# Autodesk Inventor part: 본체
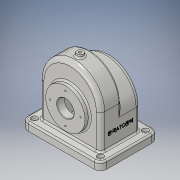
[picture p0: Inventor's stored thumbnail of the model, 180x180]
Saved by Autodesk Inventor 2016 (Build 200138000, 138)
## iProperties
Created: 2017-11
Part Number: 본체
Material: 알루미늄 6061
Document SubType Name: Modeling
Designer: Administrator
Density: 2.7 g/cm^3
Appearance: 알루미늄 - 평지
Mass: 1074.96 g
Surface Area: 1183.3 cm^2
Volume: 398.134 cm^3
Author: Administrator
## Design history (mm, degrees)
sketch "스케치2"
  geometry: L1 (55, 75)-(-55, 75); L2 (-55, 75)-(-55, -75); L3 (-55, -75)-(55, -75); L4 (55, -75)-(55, 75); L5 (55, 75)-(-55, -75); L6 (-55, 75)-(55, -75); 1 further point
  constraints: 12 end point, 2 midpoint, 2 parallel, 1 horizontal, 1 perpendicular
  dimensions: "d1" = 110 distance of L2.end L3.end; "d2" = 150 distance of L3.end L1.start
extrude "돌출1" new body sketch "스케치2" distance "d3" = 15; taper "d4" = 0 deg
fillet "모깎기1" dims "d5" = 12
sketch "스케치3"
  geometry: A1 r 12 centre (-43, -63) between (-55, -63) and (-43, -75) reference; A2 r 12 centre (-43, 63) between (-43, 75) and (-55, 63) reference; A3 r 12 centre (43, -63) between (43, -75) and (55, -63) reference; A4 r 12 centre (43, 63) between (55, 63) and (43, 75) reference; 5 further points
  constraints: 4 coincident
hole "구멍1" sketch "스케치3" at (-43, -63), (43, -63), (43, 63), (-43, 63) diameter "d6" = 5; stored, may be unused: countersink angle "d10" = 90 deg, drill point angle "d12" = 118 deg; dims "d7" = 6, "d8" = 12, "d9" = 5, "d11" = 12
fillet "모깎기2" dims "d13" = 3
sketch "스케치6"
  geometry: L1 (38, -58)-(-38, -58); L2 (-38, -58)-(-38, 58); L3 (-38, 58)-(38, 58); L4 (38, 58)-(38, -58); L5 (38, -58)-(-38, 58); L6 (-38, -58)-(38, 58); 1 further point
  constraints: 12 end point, 2 midpoint, 2 parallel, 1 horizontal, 1 perpendicular
  dimensions: "d14" = 116 distance of L1.end L2.end; "d15" = 76 distance of L1.start L1.end
extrude "돌출2" join sketch "스케치6" distance "d16" = 65; taper "d17" = 0 deg
sketch "스케치8"
  geometry: L1 (-5, -15)-(121, -15) reference; L2 (0, 65)-(116, 65) reference; A1 r 58 centre (58, 65) between (116, 65) and (0, 65); 3 further points
  constraints: 2 midpoint, 2 point on circle, 2 point on line, 1 centre point, 1 vertical alignment
  dimensions: "d21" = 116 diameter of A1; "d29" = 0 distance of point (58, 65) A1.centre
extrude "돌출3" join sketch "스케치8" distance "d22" = 38; taper "d23" = 0 deg
sketch "스케치9"
  geometry: L1 (-5, -15)-(121, -15) reference; C1 r 37.5 at (58, 50); 2 further points
  constraints: 1 centre point, 1 midpoint, 1 vertical alignment
  dimensions: "d25" = 75 diameter of C1; "d39" = 65 distance from line of L1 C1.centre
extrude "돌출4" join sketch "스케치9" distance "d26" = 9; taper "d27" = 0 deg
sketch "스케치10"
  geometry: L1 (-17, 42)-(133, 42); L2 (133, 42)-(133, 71.41); L3 (133, 71.41)-(-17, 71.41); L4 (-17, 71.41)-(-17, 42); L5 (-17, 42)-(133, 71.41); L6 (133, 42)-(-17, 71.41); L7 (-5, -15)-(121, -15) reference; L8 (0, 65)-(116, 65) reference; 7 further points
  constraints: 12 end point, 4 midpoint, 2 parallel, 1 horizontal, 1 perpendicular, 1 vertical alignment, 1 other
  dimensions: "d30" = 57 distance between parallel lines of L1 L7; "d31" = 150 distance of L2.end L3.end; "d32" = 29.40983 distance of L1.end L2.end
extrude "돌출5" cut sketch "스케치10" distance "d33" = 38; taper "d34" = 0 deg
sketch "스케치12"
  geometry: L1 (-5, -15)-(121, -15) reference; L2 (116, 42)-(0, 42) reference; A1 r 58 centre (58, 42) between (116, 42) and (0, 42); 2 further points
  constraints: 2 midpoint, 2 point on circle, 2 point on line, 1 centre point, 1 vertical alignment
  dimensions: "d35" = 116 diameter of A1
extrude "돌출6" join sketch "스케치12" distance "d36" = 38; taper "d37" = 0 deg
sketch "스케치13"
  geometry: L1 (-5, -15)-(121, -15) reference; C1 r 31 at (58, 50); 1 further point
  constraints: 1 centre point
  dimensions: "d38" = 62 diameter of C1; "d40" = 65 distance from line of L1 C1.centre
extrude "돌출7" join sketch "스케치13" distance "d41" = 10; taper "d42" = 0 deg
sketch "스케치14"
  geometry: C1 r 16 at (0, 0); C2 r 31 at (0, 0) reference; 1 further point
  constraints: 1 centre point, 1 concentric
  dimensions: "d43" = 32 diameter of C1
extrude "돌출8" cut sketch "스케치14" stored distance "d44" = 10; taper "d45" = 0 deg
node "작업 평면1"
sketch "스케치16"
  geometry: L1 (116, 0)-(116, 65) reference; L2 (0, 0)-(0, 65) reference; L3 (5, 0)-(5, 42); L4 (111, 0)-(111, 42); L5 (5, 0)-(5, -15); L6 (5, -15)-(111, -15); L7 (111, -15)-(111, 0); A1 r 58 centre (58, 42) between (116, 42) and (0, 42) reference; A2 r 53 centre (58, 42) between (111, 42) and (5, 42); 1 further point
  constraints: 10 end point, 2 parallel, 2 perpendicular, 2 point on circle, 1 centre point, 1 midpoint, 1 vertical
  dimensions: "d48" = 5 radial gap between concentric circles of A1 A2; "d49" = 5 distance between parallel lines of L2 L3; "d50" = 5 distance between parallel lines of L1 L4
extrude "돌출9" cut sketch "스케치16" distance "d51" = 38; taper "d52" = 0 deg
sketch "스케치17"
  geometry: 1 further point
sketch "스케치19"
  geometry: L1 (0, 0)-(0, 65) reference; L2 (116, 0)-(116, 65) reference; L3 (5, 0)-(5, 65); L4 (111, 65)-(111, 0); L5 (5, 0)-(5, -15); L6 (5, -15)-(111, -15); L7 (111, -15)-(111, 0); A1 r 58 centre (58, 65) between (116, 65) and (0, 65) reference; A2 r 53 centre (58, 65) between (111, 65) and (5, 65); 2 further points
  constraints: 10 end point, 2 perpendicular, 2 point on circle, 1 centre point, 1 coincident, 1 midpoint, 1 vertical, 2 other
  dimensions: "d56" = 5 radial gap between concentric circles of A1 A2
extrude "돌출11" cut sketch "스케치19" distance "d57" = 28; taper "d58" = 0 deg
sketch "스케치20"
  geometry: L1 (-63, -65)-(63, -65) reference; C1 r 16 at (0, 0) reference; 3 further points
  constraints: 1 midpoint, 1 vertical alignment
  dimensions: "d59" = 29 distance of point (0, 29) C1.centre
hole "구멍2" sketch "스케치20" at (0, 29) diameter "d60" = 3; stored, may be unused: countersink angle "d64" = 90 deg, drill point angle "d66" = 118 deg; dims "d61" = 6, "d62" = 4, "d63" = 2, "d65" = 8
node "작업 평면2"
sketch "스케치21"
  geometry: L1 (-38, 58)-(-38, -58) reference; L2 (0, 58)-(0, -58) reference; C1 r 6 at (-19, 0); 2 further points
  constraints: 1 centre point, 1 horizontal alignment, 1 midpoint
  dimensions: "d71" = 12 diameter of C1; "d72" = 19 distance from line of L2 C1.centre
extrude "돌출12" join sketch "스케치21" distance "d73" = 3; taper "d75" = 0 deg; dims "d74" = 6, "d76" = 0
sketch "스케치24"
  geometry: C1 r 2.5 at (0, 0); C2 r 6 at (0, 0) reference; 1 further point
  constraints: 1 centre point, 1 concentric
  dimensions: "d77" = 5 diameter of C1
hole "구멍3" sketch "스케치24" at (0, 0) diameter "d78" = 5; stored, may be unused: countersink angle "d82" = 90 deg, drill point angle "d84" = 118 deg; dims "d79" = 6, "d80" = 4, "d81" = 2, "d83" = 8
sketch "스케치25"
  geometry: C1 r 16 at (0, 0) reference; 2 further points
  dimensions: "d87" = 26 distance of C1.centre point (0, 26)
hole "구멍4" sketch "스케치25" at (0, 26) diameter "d88" = 3; stored, may be unused: countersink angle "d92" = 90 deg, drill point angle "d94" = 118 deg; dims "d89" = 6, "d90" = 4, "d91" = 2, "d93" = 8
chamfer "모따기1" distance "d98" = 1; stored, may be unused: second distance "d99" = 2, angle "d100" = 45 deg
fillet "모깎기5" dims "d101" = 3
sketch "스케치27"
  geometry: L1 (-35, 23)-(-35, -39) reference; L2 (-40, -57)-(46, -57) reference; 2 further points
  constraints: 1 other
  dimensions: "d102" = 38 distance from line of L1 point (3, -17); "d103" = 40 distance from line of L2 point (3, -17)
feature "엠보싱1" sketch "스케치27" dims "d104" = 0.5, "d105" = 0
fillet "모깎기6" dims "d106" = 8
fillet "모깎기7" dims "d107" = 8
fillet "모깎기8" dims "d108" = 3
fillet "모깎기9" dims "d109" = 3
fillet "모깎기10" dims "d110" = 3
fillet "모깎기11" dims "d111" = 3
node "솔리드1"
pattern_circular "원형 패턴1" dims angle "d68" = 360 deg
pattern_circular "원형 패턴2" dims angle "d96" = 360 deg
other parameters: "d47" = -5
